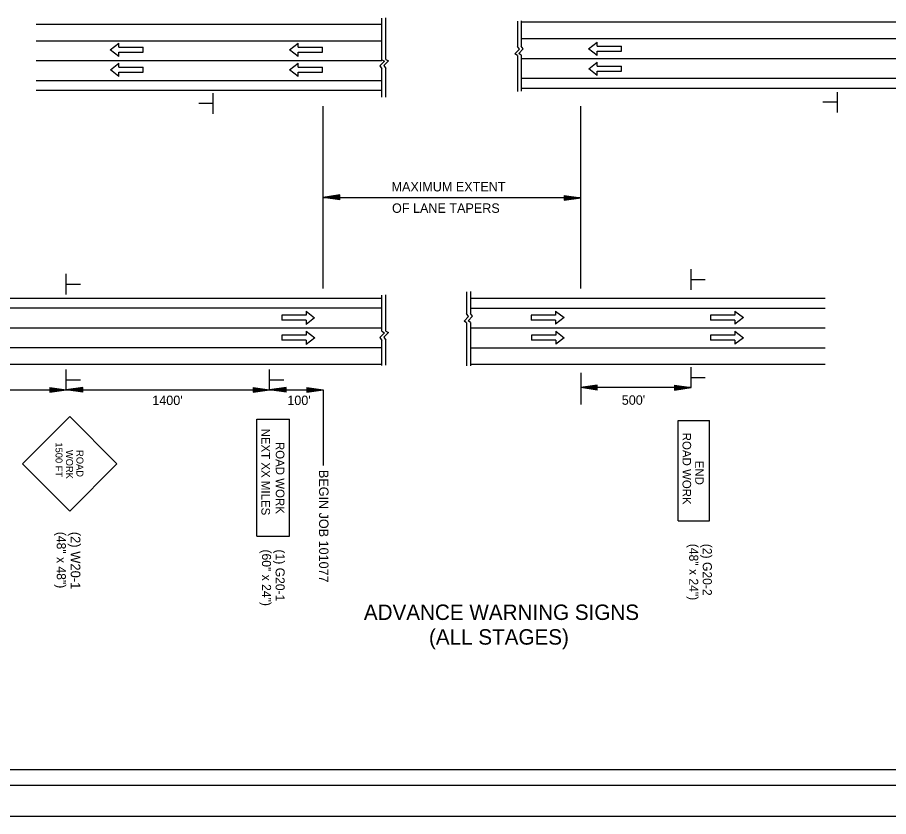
# Model space of a CAD drawing. Extents: x 13528 to 25043, y 7635 to 10612.
# Drawn here: x 14107 to 14665, y 9545 to 10057 of the extents above; entities that cross this region are included whole.
import ezdxf

# ---------------------------------------------------------------- set-up
doc = ezdxf.new("R2010")
doc.units = 0
for name, color, linetype in [('Default', 7, 'Continuous'), ('R_Border', 7, 'Continuous'), ('R_Border Title', 7, 'Continuous'), ('R_Draft', 7, 'Continuous'), ('R_No Plot', 7, 'Continuous'), ('R_Revision Date Text', 7, 'Continuous')]:
    doc.layers.add(name, color=color, linetype=linetype)

msp = doc.modelspace()

# ---------------------------------------------------------------- linework, layer by layer
at = {"layer": 'Default'}
for p, q in [((14118.5, 10052.7), (14340.14, 10052.7)), ((14340.14, 10029.94), (14340.14, 10056.6)), ((14340.14, 10029.94), (14340.14, 10056.6)), ((14342.69, 10030.12), (14342.69, 10056.78)), ((14342.69, 10030.12), (14342.69, 10056.78)), ((14426.86, 10054.65), (14426.86, 10038.49)), ((14429.41, 10054.83), (14429.41, 10038.67)), ((15016.52, 10053.89), (14429.41, 10053.89)), ((14118.5, 10042.1), (14340.14, 10042.1)), ((15016.52, 10043.3), (14429.41, 10043.3)), ((14166.05, 10036.28), (14171.54, 10040.52)), ((14171.54, 10032.04), (14166.05, 10036.28)), ((14171.54, 10037.87), (14171.54, 10040.52)), ((14171.54, 10037.87), (14187.13, 10037.87)), ((14187.13, 10034.69), (14187.13, 10037.87)), ((14280.85, 10036.28), (14286.35, 10040.52)), ((14286.35, 10032.04), (14280.85, 10036.28)), ((14286.35, 10037.87), (14286.35, 10040.52)), ((14286.35, 10037.87), (14301.93, 10037.87)), ((14301.93, 10034.69), (14301.93, 10037.87)), ((14472.51, 10036.97), (14478.01, 10041.21)), ((14478.01, 10032.73), (14472.51, 10036.97)), ((14478.01, 10038.56), (14478.01, 10041.21)), ((14478.01, 10038.56), (14493.59, 10038.56)), ((14493.59, 10035.38), (14493.59, 10038.56)), ((14171.54, 10034.69), (14187.13, 10034.69)), ((14171.54, 10032.04), (14171.54, 10034.69)), ((14286.35, 10034.69), (14301.93, 10034.69)), ((14286.35, 10032.04), (14286.35, 10034.69)), ((14426.86, 10032.68), (14426.86, 10009.5)), ((14429.41, 10032.86), (14429.41, 10009.68)), ((15016.52, 10030.59), (14429.41, 10030.59)), ((14478.01, 10035.38), (14493.59, 10035.38)), ((14478.01, 10032.73), (14478.01, 10035.38)), ((14118.5, 10029.39), (14340.14, 10029.39)), ((14166.13, 10023.46), (14171.63, 10027.7)), ((14171.63, 10025.05), (14171.63, 10027.7)), ((14171.63, 10025.05), (14187.21, 10025.05)), ((14187.21, 10021.87), (14187.21, 10025.05)), ((14280.93, 10023.46), (14286.43, 10027.7)), ((14286.43, 10025.05), (14286.43, 10027.7)), ((14286.43, 10025.05), (14302.02, 10025.05)), ((14302.02, 10021.87), (14302.02, 10025.05)), ((14472.59, 10024.15), (14478.09, 10028.38)), ((14478.09, 10025.73), (14478.09, 10028.38)), ((14478.09, 10025.73), (14493.68, 10025.73)), ((14493.68, 10022.56), (14493.68, 10025.73)), ((14171.63, 10019.22), (14166.13, 10023.46)), ((14171.63, 10021.87), (14187.21, 10021.87)), ((14171.63, 10019.22), (14171.63, 10021.87)), ((14286.43, 10019.22), (14280.93, 10023.46)), ((14286.43, 10021.87), (14302.02, 10021.87)), ((14286.43, 10019.22), (14286.43, 10021.87)), ((14340.14, 10005.85), (14340.14, 10024.13)), ((14340.14, 10005.85), (14340.14, 10024.13)), ((14342.69, 10006.03), (14342.69, 10024.31)), ((14342.69, 10006.03), (14342.69, 10024.31)), ((14478.09, 10019.91), (14472.59, 10024.15)), ((14478.09, 10022.56), (14493.68, 10022.56)), ((14478.09, 10019.91), (14478.09, 10022.56)), ((14118.5, 10016.68), (14340.14, 10016.68)), ((15016.52, 10017.87), (14429.41, 10017.87)), ((14118.5, 10010.32), (14340.14, 10010.32)), ((15016.52, 10011.52), (14429.41, 10011.52)), ((14302.47, 9883.27), (14302.47, 10000.06)), ((14467.51, 9883.27), (14467.51, 10000.06)), ((14302.47, 9941.67), (14467.51, 9941.67)), ((14394.33, 9881.23), (14394.33, 9867.18)), ((14396.88, 9881.41), (14396.88, 9867.36)), ((13753.03, 9877.2), (14340.14, 9877.2)), ((14340.14, 9855.86), (14340.14, 9879.04)), ((14342.69, 9856.04), (14342.69, 9879.22)), ((14624.13, 9876.94), (14396.88, 9876.94)), ((13753.03, 9870.84), (14340.14, 9870.84)), ((14291.46, 9868.81), (14291.46, 9866.16)), ((14291.46, 9868.81), (14296.96, 9864.57)), ((14624.13, 9870.58), (14396.88, 9870.58)), ((14451.36, 9868.85), (14451.36, 9866.2)), ((14451.36, 9868.85), (14456.86, 9864.61)), ((14566.16, 9868.85), (14566.16, 9866.2)), ((14566.16, 9868.85), (14571.66, 9864.61)), ((14291.46, 9866.16), (14275.87, 9866.16)), ((14275.87, 9866.16), (14275.87, 9862.98)), ((14291.46, 9862.98), (14275.87, 9862.98)), ((14296.96, 9864.57), (14291.46, 9860.33)), ((14291.46, 9862.98), (14291.46, 9860.33)), ((14451.36, 9866.2), (14435.77, 9866.2)), ((14435.77, 9866.2), (14435.77, 9863.02)), ((14451.36, 9863.02), (14435.77, 9863.02)), ((14456.86, 9864.61), (14451.36, 9860.37)), ((14451.36, 9863.02), (14451.36, 9860.37)), ((14566.16, 9866.2), (14550.58, 9866.2)), ((14550.58, 9866.2), (14550.58, 9863.02)), ((14566.16, 9863.02), (14550.58, 9863.02)), ((14571.66, 9864.61), (14566.16, 9860.37)), ((14566.16, 9863.02), (14566.16, 9860.37)), ((13753.03, 9858.13), (14340.14, 9858.13)), ((14394.33, 9861.37), (14394.33, 9833.8)), ((14396.88, 9861.55), (14396.88, 9833.8)), ((14624.13, 9857.87), (14396.88, 9857.87)), ((14291.54, 9853.34), (14275.96, 9853.34)), ((14275.96, 9853.34), (14275.96, 9850.16)), ((14291.54, 9855.99), (14291.54, 9853.34)), ((14291.54, 9855.99), (14297.04, 9851.75)), ((14297.04, 9851.75), (14291.54, 9847.51)), ((14451.44, 9853.37), (14435.86, 9853.37)), ((14435.86, 9853.37), (14435.86, 9850.2)), ((14451.44, 9856.02), (14451.44, 9853.37)), ((14451.44, 9856.02), (14456.94, 9851.78)), ((14456.94, 9851.78), (14451.44, 9847.55)), ((14566.25, 9853.37), (14550.66, 9853.37)), ((14550.66, 9853.37), (14550.66, 9850.2)), ((14566.25, 9856.02), (14566.25, 9853.37)), ((14566.25, 9856.02), (14571.75, 9851.78)), ((14571.75, 9851.78), (14566.25, 9847.55)), ((14291.54, 9850.16), (14275.96, 9850.16)), ((14291.54, 9850.16), (14291.54, 9847.51)), ((14340.14, 9833.88), (14340.14, 9850.05)), ((14342.69, 9834.06), (14342.69, 9850.23)), ((14451.44, 9850.2), (14435.86, 9850.2)), ((14451.44, 9850.2), (14451.44, 9847.55)), ((14566.25, 9850.2), (14550.66, 9850.2)), ((14566.25, 9850.2), (14566.25, 9847.55)), ((13753.03, 9845.42), (14340.14, 9845.42)), ((14624.13, 9845.15), (14396.88, 9845.15)), ((13753.03, 9834.82), (14340.14, 9834.82)), ((14624.13, 9834.56), (14396.88, 9834.56)), ((14467.51, 9829.35), (14467.51, 9809.01)), ((14046.91, 9818.34), (14137.88, 9818.34)), ((14137.88, 9818.34), (14268.17, 9818.34)), ((14268.17, 9818.34), (14302.47, 9818.34)), ((14302.47, 9818.34), (14302.47, 9769.78)), ((14538.14, 9819.78), (14467.51, 9819.78))]:
    msp.add_line(p, q, dxfattribs=at)
for points in [[(14426.86, 10032.68), (14425.22, 10033.65), (14428.14, 10036.66), (14426.86, 10038.49)], [(14429.41, 10032.86), (14427.78, 10033.83), (14430.69, 10036.84), (14429.41, 10038.67)], [(14342.69, 10030.12), (14344.32, 10029.15), (14341.41, 10026.14), (14342.69, 10024.31)], [(14342.69, 10030.12), (14344.32, 10029.15), (14341.41, 10026.14), (14342.69, 10024.31)], [(14340.14, 10029.94), (14341.77, 10028.97), (14338.86, 10025.96), (14340.14, 10024.13)], [(14340.14, 10029.94), (14341.77, 10028.97), (14338.86, 10025.96), (14340.14, 10024.13)], [(14394.33, 9861.37), (14392.7, 9862.34), (14395.61, 9865.35), (14394.33, 9867.18)], [(14396.88, 9861.55), (14395.25, 9862.53), (14398.17, 9865.54), (14396.88, 9867.36)], [(14340.14, 9855.86), (14341.77, 9854.88), (14338.86, 9851.88), (14340.14, 9850.05)], [(14342.69, 9856.04), (14344.32, 9855.07), (14341.41, 9852.06), (14342.69, 9850.23)]]:
    msp.add_lwpolyline(points, dxfattribs=at)
at = {"layer": 'R_Border'}
for p, q in [((14231.83, 10008.4), (14231.83, 9995.32)), ((14631.67, 10009.19), (14631.67, 9996.1)), ((14631.48, 10002.67), (14622.54, 10002.67)), ((14231.64, 10001.89), (14222.7, 10001.89)), ((14137.88, 9879.53), (14137.88, 9892.62)), ((14538.14, 9882.52), (14538.14, 9895.61)), ((14138.07, 9886.04), (14147, 9886.05)), ((14538.33, 9889.03), (14547.26, 9889.03)), ((14137.88, 9818.34), (14137.88, 9831.43)), ((14268.17, 9818.34), (14268.17, 9831.43)), ((14538.14, 9819.78), (14538.14, 9832.87)), ((14138.07, 9824.86), (14147, 9824.86)), ((14268.36, 9824.86), (14277.29, 9824.86)), ((14538.33, 9826.29), (14547.26, 9826.3)), ((14109.76, 9771), (14140.05, 9801.31)), ((14170.35, 9771), (14140.05, 9801.31)), ((14529.84, 9734.31), (14529.84, 9798.67)), ((14529.84, 9798.67), (14550.06, 9798.67)), ((14550.06, 9734.31), (14550.06, 9798.67)), ((14140.05, 9740.69), (14109.76, 9771)), ((14140.05, 9740.69), (14170.35, 9771)), ((14529.84, 9734.31), (14550.06, 9734.31))]:
    msp.add_line(p, q, dxfattribs=at)
at = {"layer": 'R_Border Title'}
for p, q in [((14313.07, 9943.26), (14302.47, 9941.67)), ((14313.07, 9940.08), (14302.47, 9941.67)), ((14313.07, 9942.99), (14304.24, 9941.67)), ((14313.07, 9940.34), (14304.24, 9941.67)), ((14313.07, 9942.72), (14306.06, 9941.67)), ((14313.07, 9940.61), (14306.06, 9941.67)), ((14313.07, 9942.46), (14307.83, 9941.67)), ((14313.07, 9940.88), (14307.83, 9941.67)), ((14313.07, 9942.19), (14309.62, 9941.67)), ((14313.07, 9941.15), (14309.62, 9941.67)), ((14313.07, 9941.92), (14311.39, 9941.67)), ((14313.07, 9941.42), (14311.39, 9941.67)), ((14313.07, 9940.08), (14313.07, 9943.26)), ((14456.92, 9942.99), (14467.51, 9941.4)), ((14456.92, 9942.99), (14456.92, 9939.81)), ((14456.92, 9942.73), (14465.74, 9941.4)), ((14456.92, 9942.46), (14463.92, 9941.4)), ((14456.92, 9942.19), (14462.15, 9941.4)), ((14456.92, 9941.92), (14460.36, 9941.4)), ((14456.92, 9941.65), (14458.59, 9941.4)), ((14456.92, 9939.81), (14467.51, 9941.4)), ((14456.92, 9940.88), (14460.36, 9941.4)), ((14456.92, 9940.35), (14463.92, 9941.4)), ((14456.92, 9940.08), (14465.74, 9941.4)), ((14456.92, 9940.61), (14462.15, 9941.4)), ((14456.92, 9941.15), (14458.59, 9941.4)), ((14127.28, 9819.93), (14137.88, 9818.34)), ((14127.28, 9819.93), (14127.28, 9816.76)), ((14127.28, 9819.67), (14136.11, 9818.34)), ((14127.28, 9819.4), (14134.29, 9818.34)), ((14127.28, 9819.13), (14132.52, 9818.34)), ((14127.28, 9818.86), (14130.73, 9818.34)), ((14127.28, 9818.59), (14128.96, 9818.34)), ((14127.28, 9816.76), (14137.88, 9818.34)), ((14127.28, 9817.83), (14130.73, 9818.34)), ((14127.28, 9817.29), (14134.29, 9818.34)), ((14127.28, 9817.02), (14136.11, 9818.34)), ((14127.28, 9817.56), (14132.52, 9818.34)), ((14127.28, 9818.1), (14128.96, 9818.34)), ((14148.47, 9819.93), (14137.88, 9818.34)), ((14148.47, 9816.76), (14137.88, 9818.34)), ((14148.47, 9819.67), (14139.65, 9818.34)), ((14148.47, 9817.02), (14139.65, 9818.34)), ((14148.47, 9819.4), (14141.47, 9818.34)), ((14148.47, 9817.29), (14141.47, 9818.34)), ((14148.47, 9819.13), (14143.23, 9818.34)), ((14148.47, 9817.56), (14143.23, 9818.34)), ((14148.47, 9818.86), (14145.03, 9818.34)), ((14148.47, 9817.83), (14145.03, 9818.34)), ((14148.47, 9818.59), (14146.8, 9818.34)), ((14148.47, 9818.1), (14146.8, 9818.34)), ((14148.47, 9816.76), (14148.47, 9819.93)), ((14257.58, 9819.93), (14268.17, 9818.34)), ((14257.58, 9819.93), (14257.58, 9816.76)), ((14257.58, 9819.67), (14266.4, 9818.34)), ((14257.58, 9819.4), (14264.58, 9818.34)), ((14257.58, 9819.13), (14262.81, 9818.34)), ((14257.58, 9818.86), (14261.02, 9818.34)), ((14257.58, 9818.59), (14259.25, 9818.34)), ((14257.58, 9816.76), (14268.17, 9818.34)), ((14257.58, 9817.83), (14261.02, 9818.34)), ((14257.58, 9817.29), (14264.58, 9818.34)), ((14257.58, 9817.02), (14266.4, 9818.34)), ((14257.58, 9817.56), (14262.81, 9818.34)), ((14257.58, 9818.1), (14259.25, 9818.34)), ((14278.76, 9819.93), (14268.17, 9818.34)), ((14278.76, 9816.76), (14268.17, 9818.34)), ((14278.76, 9819.67), (14269.94, 9818.34)), ((14278.76, 9817.02), (14269.94, 9818.34)), ((14278.76, 9819.4), (14271.76, 9818.34)), ((14278.76, 9817.29), (14271.76, 9818.34)), ((14278.76, 9819.13), (14273.52, 9818.34)), ((14278.76, 9817.56), (14273.52, 9818.34)), ((14278.76, 9818.86), (14275.32, 9818.34)), ((14278.76, 9817.83), (14275.32, 9818.34)), ((14278.76, 9818.59), (14277.09, 9818.34)), ((14278.76, 9818.1), (14277.09, 9818.34)), ((14278.76, 9816.76), (14278.76, 9819.93)), ((14291.88, 9819.93), (14302.47, 9818.34)), ((14291.88, 9819.93), (14291.88, 9816.76)), ((14291.88, 9819.67), (14300.7, 9818.34)), ((14291.88, 9819.4), (14298.88, 9818.34)), ((14291.88, 9819.13), (14297.12, 9818.34)), ((14291.88, 9818.86), (14295.32, 9818.34)), ((14291.88, 9818.59), (14293.55, 9818.34)), ((14291.88, 9816.76), (14302.47, 9818.34)), ((14291.88, 9817.83), (14295.32, 9818.34)), ((14291.88, 9817.29), (14298.88, 9818.34)), ((14291.88, 9817.02), (14300.7, 9818.34)), ((14291.88, 9817.56), (14297.12, 9818.34)), ((14291.88, 9818.1), (14293.55, 9818.34)), ((14478.1, 9821.37), (14467.51, 9819.78)), ((14478.1, 9818.19), (14467.51, 9819.78)), ((14478.1, 9821.11), (14469.28, 9819.78)), ((14478.1, 9818.46), (14469.28, 9819.78)), ((14478.1, 9820.84), (14471.1, 9819.78)), ((14478.1, 9818.73), (14471.1, 9819.78)), ((14478.1, 9820.57), (14472.87, 9819.78)), ((14478.1, 9818.99), (14472.87, 9819.78)), ((14478.1, 9820.3), (14474.66, 9819.78)), ((14478.1, 9819.27), (14474.66, 9819.78)), ((14478.1, 9820.03), (14476.43, 9819.78)), ((14478.1, 9819.53), (14476.43, 9819.78)), ((14478.1, 9818.19), (14478.1, 9821.37)), ((14527.54, 9821.37), (14538.14, 9819.78)), ((14527.54, 9821.37), (14527.54, 9818.19)), ((14527.54, 9821.11), (14536.37, 9819.78)), ((14527.54, 9820.84), (14534.55, 9819.78)), ((14527.54, 9820.57), (14532.78, 9819.78)), ((14527.54, 9820.3), (14530.99, 9819.78)), ((14527.54, 9820.03), (14529.22, 9819.78)), ((14527.54, 9818.19), (14538.14, 9819.78)), ((14527.54, 9819.26), (14530.99, 9819.78)), ((14527.54, 9818.73), (14534.55, 9819.78)), ((14527.54, 9818.46), (14536.37, 9819.78)), ((14527.54, 9818.99), (14532.78, 9819.78)), ((14527.54, 9819.53), (14529.22, 9819.78))]:
    msp.add_line(p, q, dxfattribs=at)
at = {"layer": 'R_Draft'}
msp.add_line((15171.12, 9564.77), (13590.22, 9564.77), dxfattribs=at)
at = {"layer": 'R_No Plot'}
for p, q in [((14260.05, 9724.52), (14260.05, 9799.56)), ((14260.05, 9799.56), (14280.91, 9799.56)), ((14280.91, 9724.52), (14280.91, 9799.56)), ((14260.05, 9724.52), (14280.91, 9724.52))]:
    msp.add_line(p, q, dxfattribs=at)
at = {"layer": 'R_Revision Date Text'}
for points in [[(13528.19, 10611.55), (15194.89, 10611.55), (15194.89, 9544.86), (13528.19, 9544.86)], [(13600.22, 10582.07), (14847.92, 10582.07), (14847.92, 10532.67), (14935.62, 10532.67), (15056.12, 10532.67), (15056.12, 10421.01), (15161.12, 10421.01), (15161.12, 9574.77), (13600.22, 9574.77)], [(13600.22, 10068.42), (15161.12, 10068.42), (15161.12, 9574.77), (13600.22, 9574.77)]]:
    msp.add_lwpolyline(points, close=True, dxfattribs=at)

# ---------------------------------------------------------------- texts
at = {"layer": 'Default'}
for s, height, p in [('MAXIMUM EXTENT', 6.0315, (14346.25, 9945.52)), ('OF LANE TAPERS', 6.0315, (14346.56, 9931.79)), ("1400'", 6.031, (14192.95, 9808.62)), ("100'", 6.031, (14279.48, 9808.62)), ("500'", 6.031, (14493.77, 9808.79)), ('ADVANCE WARNING SIGNS', 9.8877, (14328.52, 9670.87)), ('(ALL STAGES)', 9.8877, (14370.25, 9655.05))]:
    msp.add_text(s, height=height, dxfattribs=at).set_placement(p)
msp.add_text('BEGIN JOB 101077', height=6.0315, rotation=270, dxfattribs=at).set_placement((14299.83, 9767.01))
at = {"layer": 'R_Border'}
for s, height, rotation, p in [('NEXT XX MILES', 5.4947, 270, (14262.9, 9793.5)), ('ROAD WORK', 5.495, 270, (14532.69, 9790.88)), ('1500 FT', 4.465, 270.0006, (14130.97, 9784.66)), ('WORK', 4.464, 270, (14137.67, 9779.84)), ('ROAD', 4.465, 270.0004, (14144.37, 9779.76)), ('ROAD WORK', 5.495, 270, (14272.12, 9784.98)), ('END', 5.495, 270, (14540.8, 9772.95)), ('(48" x 48")', 5.814, 270, (14131.77, 9727.36)), ('(2) W20-1', 6.202, 270, (14140.69, 9727.36)), ('(48" x 24")', 5.814, 270, (14536.95, 9719.7)), ('(2) G20-2', 5.815, 270, (14545.67, 9719.7)), ('(60" x 24")', 5.814, 270, (14263.24, 9716.04)), ('(1) G20-1', 5.815, 270, (14271.96, 9716.04))]:
    msp.add_text(s, height=height, rotation=rotation, dxfattribs=at).set_placement(p)

doc.saveas('drawing.dxf')
